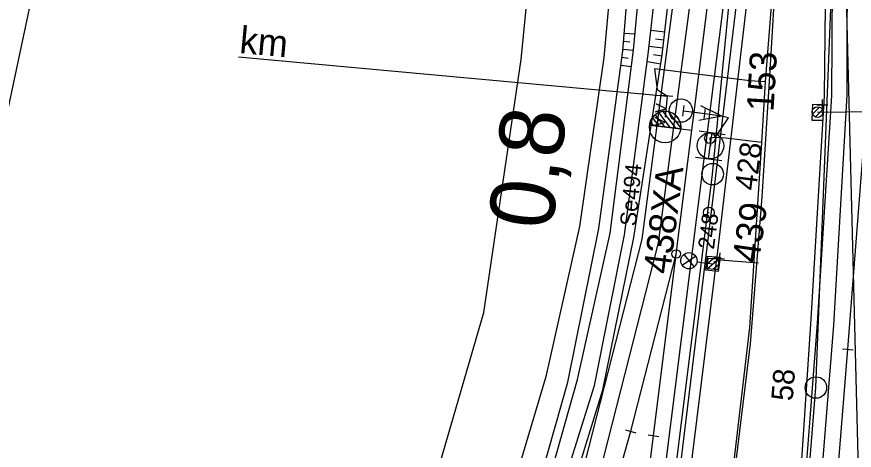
# Model space of a CAD drawing. Extents: x -598638 to -597933, y -1164002 to -1161904.
# Drawn here: x -598323.8 to -598246.1, y -1163278.4 to -1163238.1 of the extents above; entities that cross this region are included whole.
import ezdxf

# ---------------------------------------------------------------- set-up
doc = ezdxf.new("R2010")
doc.units = 0
for name, color, linetype in [('Vrstva 1', 7, 'Continuous'), ('Vrstva 11', 7, 'Continuous'), ('Vrstva 12', 7, 'Continuous'), ('Vrstva 2', 7, 'Continuous'), ('Vrstva 25', 7, 'Continuous'), ('Vrstva 26', 7, 'Continuous'), ('Vrstva 28', 7, 'Continuous'), ('Vrstva 3', 7, 'Continuous'), ('Vrstva 35', 7, 'Continuous'), ('Vrstva 4', 7, 'Continuous'), ('Vrstva 43', 7, 'Continuous'), ('Vrstva 44', 7, 'Continuous'), ('Vrstva 48', 7, 'Continuous'), ('Vrstva 49', 7, 'Continuous'), ('Vrstva 51', 7, 'Continuous'), ('Vrstva 6', 7, 'Continuous'), ('Vrstva 63', 7, 'Continuous'), ('Vrstva 7', 7, 'Continuous')]:
    doc.layers.add(name, color=color, linetype=linetype)

msp = doc.modelspace()

# ---------------------------------------------------------------- linework, layer by layer
at = {"layer": 'Vrstva 1'}
msp.add_line((-598246.649, -1163269.02), (-598244.89, -1163246.328), dxfattribs=at)
for points in [[(-598261.135, -1163248.665), (-598260.926, -1163246.987), (-598257.805, -1163221.972)], [(-598264.695, -1163277.054), (-598262.58, -1163260.169), (-598261.135, -1163248.665)], [(-598266.808, -1163276.648), (-598262.58, -1163260.169)], [(-598250.9, -1163321.936), (-598249.53, -1163304.978), (-598248.914, -1163297.297), (-598247.877, -1163284.361), (-598246.649, -1163269.02)], [(-598290.948, -1163362.176), (-598285.982, -1163344.65), (-598282.717, -1163333.052), (-598281.168, -1163327.552), (-598279.885, -1163323.01), (-598271.302, -1163292.589), (-598266.808, -1163276.648)], [(-598265.253, -1163281.456), (-598264.695, -1163277.054)]]:
    msp.add_lwpolyline(points, dxfattribs=at)
at = {"layer": 'Vrstva 11'}
for p, q in [((-598249.921, -1163247.154), (-598249.275, -1163246.508)), ((-598249.661, -1163247.424), (-598249.006, -1163246.769)), ((-598259.712, -1163261.53), (-598258.63, -1163260.626)), ((-598259.665, -1163261.003), (-598259.158, -1163260.579)), ((-598259.188, -1163261.58), (-598258.674, -1163261.151))]:
    msp.add_line(p, q, dxfattribs=at)
for points in [[(-598249.46, -1163246.97), (-598236.36, -1163246.81)], [(-598259.623, -1163260.537), (-598258.627, -1163260.627), (-598258.717, -1163261.623), (-598259.713, -1163261.533), (-598259.623, -1163260.537)]]:
    msp.add_lwpolyline(points, dxfattribs=at)
msp.add_lwpolyline([(-598259.623, -1163260.537), (-598258.627, -1163260.627), (-598258.717, -1163261.623), (-598259.713, -1163261.533)], close=True, dxfattribs=at)
msp.add_circle((-598249.46, -1163246.97), 0.5, dxfattribs=at)
at = {"layer": 'Vrstva 12'}
for points in [[(-598248.96, -1163246.25), (-598248.98, -1163247.75), (-598249.95, -1163247.76), (-598249.91, -1163246.24), (-598248.96, -1163246.25)], [(-598259.83, -1163261.68), (-598259.67, -1163260.38), (-598258.51, -1163260.47), (-598258.68, -1163261.8), (-598259.83, -1163261.68)]]:
    msp.add_lwpolyline(points, dxfattribs=at)
at = {"layer": 'Vrstva 2'}
for p, q in [((-598263.631, -1163248.354), (-598264.516, -1163247.213)), ((-598263.104, -1163248.421), (-598264.194, -1163247.018)), ((-598262.578, -1163248.487), (-598263.804, -1163246.909)), ((-598262.15, -1163248.427), (-598263.314, -1163246.927)), ((-598264.683, -1163248.221), (-598264.976, -1163247.845)), ((-598264.157, -1163248.287), (-598264.779, -1163247.486)), ((-598262.156, -1163248.54), (-598265.06, -1163248.174)), ((-598265.06, -1163248.174), (-598262.156, -1163248.539)), ((-598262.156, -1163248.539), (-598262.156, -1163248.54)), ((-598262.155, -1163248.54), (-598261.135, -1163248.665)), ((-598247.147, -1163268.98), (-598246.151, -1163269.06)), ((-598267.289, -1163276.512), (-598266.327, -1163276.784)), ((-598265.191, -1163276.991), (-598264.199, -1163277.117))]:
    msp.add_line(p, q, dxfattribs=at)
for points in [[(-598246.649, -1163269.02), (-598244.89, -1163246.328)], [(-598264.695, -1163277.054), (-598262.58, -1163260.169), (-598261.135, -1163248.665)], [(-598266.808, -1163276.648), (-598262.58, -1163260.169)]]:
    msp.add_lwpolyline(points, dxfattribs=at)
for centre, radius in [((-598263.616, -1163248.354), 1.462), ((-598262.585, -1163260.163), 0.4)]:
    msp.add_circle(centre, radius, dxfattribs=at)
msp.add_arc((-598263.608, -1163248.357), 1.464, 352.86023, 172.82108, dxfattribs=at)
at = {"layer": 'Vrstva 25'}
for p, q in [((-598259.5, -1163249.4), (-598259.4, -1163249.4)), ((-598262.029, -1163261.215), (-598260.785, -1163260.363)), ((-598261.885, -1163260.21), (-598260.915, -1163261.365)), ((-598260.658, -1163260.89), (-598259.17, -1163261.08))]:
    msp.add_line(p, q, dxfattribs=at)
for centre, radius in [((-598259.449, -1163249.397), 0.5), ((-598261.405, -1163260.792), 0.754)]:
    msp.add_circle(centre, radius, dxfattribs=at)
at = {"layer": 'Vrstva 26'}
for points in [[(-598273.816, -1163355.578), (-598271.677, -1163346.374), (-598270.289, -1163341.485), (-598268.518, -1163336.06), (-598265.457, -1163325.157), (-598262.629, -1163312.811), (-598258.667, -1163293.697), (-598257.35, -1163282.225), (-598255.678, -1163268.505), (-598254.603, -1163254.848), (-598253.891, -1163243.597), (-598253.428, -1163235.813)], [(-598254.944, -1163261.011), (-598258.507, -1163260.742), (-598259.131, -1163260.92)]]:
    msp.add_lwpolyline(points, dxfattribs=at)
at = {"layer": 'Vrstva 28'}
for points in [[(-598253.43, -1163232.8), (-598254.31, -1163244.16), (-598254.67, -1163249.79), (-598255.78, -1163266.99), (-598257.63, -1163282.82), (-598258.86, -1163294.68), (-598252.64, -1163294.8), (-598246.37, -1163296.02), (-598247.03, -1163297.8)], [(-598254.31, -1163244.16), (-598255.75, -1163244.05), (-598264.61, -1163242.96), (-598264.36, -1163244.88), (-598263.41, -1163245.48)], [(-598258.98, -1163249.34), (-598257.74, -1163247.49), (-598258.34, -1163247.34)], [(-598254.67, -1163249.79), (-598257.98, -1163249.4), (-598258.98, -1163249.34), (-598259.45, -1163249.4), (-598259.41, -1163250.1)]]:
    msp.add_lwpolyline(points, dxfattribs=at)
at = {"layer": 'Vrstva 3'}
for p, q in [((-598261.983, -1163247.353), (-598261.852, -1163246.361)), ((-598258.34, -1163247.34), (-598260.301, -1163246.383)), ((-598261.917, -1163246.857), (-598259.935, -1163247.117)), ((-598258.34, -1163247.34), (-598261.076, -1163246.976)), ((-598260, -1163247.613), (-598259.869, -1163246.621)), ((-598258.34, -1163247.34), (-598260.483, -1163247.751)), ((-598260.467, -1163248.715), (-598258.025, -1163249.043)), ((-598259.574, -1163251.321), (-598259.246, -1163248.879)), ((-598260.795, -1163251.157), (-598258.353, -1163251.485))]:
    msp.add_line(p, q, dxfattribs=at)
for centre, radius in [((-598262.154, -1163246.832), 1.084), ((-598259.409, -1163250.099), 1.232)]:
    msp.add_circle(centre, radius, dxfattribs=at)
at = {"layer": 'Vrstva 35'}
msp.add_lwpolyline([(-598255.75, -1163244.05), (-598264.61, -1163242.96)], dxfattribs=at)
at = {"layer": 'Vrstva 4'}
for points in [[(-598398.167, -1163553.239), (-598376.487, -1163515.918), (-598348.795, -1163467.979), (-598339.716, -1163452.202), (-598323.266, -1163423.236), (-598308.372, -1163396.471), (-598302.715, -1163384.123), (-598298.324, -1163372.137), (-598289.593, -1163344.221), (-598282.967, -1163321.229), (-598274.797, -1163290.285), (-598269.404, -1163272.781), (-598266.519, -1163258.633), (-598263.896, -1163241.651), (-598261.185, -1163218.05), (-598260.503, -1163217.001), (-598259.092, -1163201.513), (-598258.163, -1163186.176), (-598256.557, -1163141.317), (-598256.485, -1163129.008), (-598255.651, -1163108.451), (-598254.34, -1163087.718), (-598253.319, -1163075.132)], [(-598307.376, -1163503.64), (-598306.256, -1163500.72), (-598304.527, -1163496.743), (-598299.478, -1163486.144), (-598290.117, -1163465.204), (-598280.795, -1163442.724), (-598274.814, -1163425.66), (-598269.09, -1163405.616), (-598262.907, -1163380.487), (-598260.225, -1163366.071), (-598256.638, -1163342.661), (-598254.612, -1163322.432), (-598252.977, -1163304.928), (-598251.437, -1163287.268), (-598250.068, -1163266.224), (-598248.818, -1163245.446), (-598248.467, -1163214.545), (-598248.623, -1163173.63), (-598248.072, -1163131.254), (-598247.596, -1163128.349)], [(-598388.69, -1163572.819), (-598382.701, -1163561.089), (-598361.383, -1163524.292), (-598334.6, -1163477.579), (-598308.353, -1163432.12), (-598292.471, -1163404.257), (-598285.937, -1163390.16), (-598281.631, -1163378.652), (-598277.216, -1163365.008), (-598272.579, -1163348.284), (-598269.387, -1163336.75), (-598267.113, -1163324.869), (-598262.674, -1163291.919), (-598258.642, -1163259.137), (-598254.182, -1163220.99), (-598251.647, -1163201.068), (-598250.766, -1163187.503), (-598249.671, -1163144.519), (-598248.922, -1163130.776), (-598248.69, -1163130.313)]]:
    msp.add_lwpolyline(points, dxfattribs=at)
at = {"layer": 'Vrstva 43'}
for centre in [(-598259.208, -1163252.741), (-598249.615, -1163272.581)]:
    msp.add_circle(centre, 1, dxfattribs=at)
at = {"layer": 'Vrstva 44'}
for points in [[(-598295.758, -1163493.483), (-598278.118, -1163452.874), (-598264.209, -1163410.565), (-598254.468, -1163367.19), (-598248.62, -1163321.577), (-598253.497, -1163320.887), (-598249.615, -1163272.581), (-598247.635, -1163222.481), (-598247.486, -1163176.779), (-598247.442, -1163130.148), (-598244.014, -1163084.171), (-598235.33, -1163037.762), (-598224.817, -1163002.559), (-598219.379, -1163002.169), (-598206.652, -1162968.487), (-598191.401, -1162936.053), (-598173.754, -1162904.506), (-598155.689, -1162873.083), (-598136.14, -1162838.446), (-598116.776, -1162804.197)], [(-598280.199, -1163332.648), (-598271.397, -1163301.809), (-598265.446, -1163302.712), (-598259.208, -1163252.741), (-598251.788, -1163176.385), (-598250.383, -1163130.296), (-598247.948, -1163083.491), (-598241.007, -1163044.927)]]:
    msp.add_lwpolyline(points, dxfattribs=at)
at = {"layer": 'Vrstva 48'}
for p, q in [((-598264.949, -1163239.347), (-598263.648, -1163239.496)), ((-598266.416, -1163239.741), (-598267.414, -1163239.661)), ((-598264.513, -1163240.151), (-598263.734, -1163240.241)), ((-598266.881, -1163240.456), (-598267.474, -1163240.409)), ((-598265.116, -1163240.837), (-598263.82, -1163240.986)), ((-598266.555, -1163241.235), (-598267.534, -1163241.156)), ((-598264.681, -1163241.611), (-598263.908, -1163241.731)), ((-598267.045, -1163241.979), (-598267.627, -1163241.9)), ((-598265.294, -1163242.275), (-598264.023, -1163242.472)), ((-598266.752, -1163242.775), (-598267.727, -1163242.644))]:
    msp.add_line(p, q, dxfattribs=at)
at = {"layer": 'Vrstva 49'}
for points in [[(-598299.445, -1163361.058), (-598297.068, -1163359.059), (-598293.068, -1163343.621), (-598287.79, -1163320.649), (-598279.637, -1163288.312), (-598274.636, -1163271.434), (-598271.523, -1163257.595), (-598269.283, -1163241.904), (-598267.104, -1163218.072), (-598264.127, -1163206.783), (-598263.144, -1163204.971), (-598260.62, -1163202.843), (-598259.578, -1163186.018), (-598258.253, -1163141.176), (-598259.192, -1163127.718), (-598260.075, -1163119.279), (-598261.182, -1163115.692), (-598261.349, -1163113.122), (-598258.894, -1163101.538), (-598255.65, -1163087.809), (-598254.518, -1163075.132), (-598252.098, -1163061.479), (-598247.841, -1163044.835)], [(-598309.446, -1163203.262), (-598316.229, -1163215.539), (-598313.873, -1163217.741), (-598321.933, -1163233.799), (-598326.308, -1163254.29), (-598324.871, -1163281.374), (-598324.668, -1163290.005), (-598320.258, -1163307.426), (-598325.507, -1163312.636), (-598323.584, -1163327.934), (-598325.353, -1163339.082), (-598298.967, -1163343.623), (-598293.544, -1163316.86), (-598287.625, -1163290.34), (-598280.443, -1163265.616), (-598276.989, -1163242.095), (-598274.987, -1163221.639), (-598274.592, -1163211.298), (-598290.163, -1163206.434), (-598302.523, -1163205.338), (-598306.323, -1163207.572)], [(-598350.075, -1163469.161), (-598350.962, -1163468.642), (-598341.128, -1163451.449), (-598324.91, -1163422.41), (-598309.936, -1163395.461), (-598304.358, -1163383.215), (-598300.139, -1163371.399), (-598292.224, -1163343.911), (-598285.916, -1163320.98), (-598277.492, -1163289.124), (-598272.642, -1163272.084), (-598269.771, -1163257.778), (-598267.544, -1163241.285), (-598265.728, -1163218.657), (-598264.511, -1163217.412), (-598261.185, -1163218.05)], [(-598350.962, -1163468.642), (-598340.803, -1163451.583), (-598324.406, -1163422.648), (-598309.58, -1163395.796), (-598303.887, -1163383.446), (-598299.666, -1163371.582), (-598291.401, -1163343.859), (-598285.02, -1163321.209), (-598276.751, -1163289.495), (-598271.739, -1163271.843), (-598268.729, -1163258.218), (-598266.553, -1163241.22), (-598264.463, -1163218.64)], [(-598350.075, -1163469.161), (-598340.252, -1163451.87), (-598323.84, -1163422.849), (-598308.915, -1163396.15), (-598303.181, -1163383.749), (-598299.003, -1163371.924), (-598290.374, -1163343.997), (-598283.872, -1163321.586), (-598275.648, -1163289.867), (-598270.185, -1163272.379), (-598267.391, -1163258.396), (-598265.172, -1163241.341), (-598262.635, -1163218.663), (-598264.463, -1163218.64)]]:
    msp.add_lwpolyline(points, dxfattribs=at)
at = {"layer": 'Vrstva 51'}
for points in [[(-598397.431, -1163553.318), (-598375.745, -1163515.943), (-598348.098, -1163468.333), (-598322.38, -1163423.533), (-598307.542, -1163396.818), (-598301.86, -1163384.541), (-598297.285, -1163372.341), (-598293.283, -1163359.379), (-598288.845, -1163344.448), (-598282.25, -1163321.235), (-598273.825, -1163290.423), (-598265.756, -1163258.778), (-598260.545, -1163219.203), (-598259.744, -1163217.171), (-598258.57, -1163201.891), (-598257.659, -1163186.255), (-598256.038, -1163142.193), (-598255.793, -1163128.623), (-598255.065, -1163108.27), (-598253.781, -1163088.998), (-598252.62, -1163075.466)], [(-598396.078, -1163554.151), (-598374.443, -1163516.599), (-598347.031, -1163469.014), (-598321.218, -1163424.261), (-598306.253, -1163397.723), (-598300.608, -1163385.153), (-598295.814, -1163372.93), (-598291.849, -1163359.988), (-598287.46, -1163344.41), (-598281.154, -1163322.32), (-598272.412, -1163291.197), (-598264.229, -1163259.135), (-598258.972, -1163219.27), (-598257.327, -1163201.644), (-598256.369, -1163186.491), (-598254.79, -1163142.649), (-598254.397, -1163128.629), (-598253.571, -1163108.317), (-598252.585, -1163090.153), (-598250.983, -1163076.012)], [(-598384.985, -1163560.822), (-598363.176, -1163523.063), (-598335.955, -1163475.581), (-598310.179, -1163431.066), (-598295.149, -1163404.135), (-598288.465, -1163389.583), (-598283.96, -1163377.815), (-598279.772, -1163364.473), (-598275.196, -1163348.33), (-598271.933, -1163336.198), (-598269.31, -1163324.265), (-598265.084, -1163292.029), (-598261.053, -1163259.678), (-598256.104, -1163220.296), (-598254.426, -1163201.671), (-598253.667, -1163187.936), (-598252.018, -1163143.494), (-598251.534, -1163128.863), (-598250.791, -1163108.998), (-598250.069, -1163094.383), (-598248.218, -1163076.729)], [(-598305.922, -1163504.285), (-598297.335, -1163487.137), (-598287.92, -1163465.981), (-598279.035, -1163443.103), (-598273.208, -1163425.978), (-598267.2, -1163406.108), (-598261.011, -1163380.887), (-598258.166, -1163366.304), (-598254.569, -1163343.143), (-598252.435, -1163322.084), (-598250.965, -1163305.051), (-598249.488, -1163286.133), (-598247.962, -1163266.793), (-598246.718, -1163245.404), (-598246.637, -1163214.417), (-598246.633, -1163173.748), (-598246.347, -1163129.422), (-598245.484, -1163112.939), (-598244.076, -1163096.672), (-598241.475, -1163076.865)], [(-598298.888, -1163486.593), (-598289.113, -1163465.583), (-598279.905, -1163442.964), (-598274.107, -1163425.699), (-598268.268, -1163405.757), (-598262.238, -1163380.596), (-598259.701, -1163366.461), (-598255.999, -1163342.847), (-598253.859, -1163322.319), (-598252.407, -1163304.609), (-598250.982, -1163286.31), (-598249.458, -1163266.6), (-598248.128, -1163245.447), (-598247.963, -1163214.31), (-598248.01, -1163173.778), (-598247.475, -1163130.652), (-598247.596, -1163128.349), (-598246.685, -1163112.866), (-598245.177, -1163096.514), (-598242.921, -1163076.624)], [(-598389.422, -1163572.47), (-598383.242, -1163561.018), (-598361.933, -1163523.985), (-598335.337, -1163477.363), (-598309.065, -1163431.797), (-598293.626, -1163404.644), (-598286.924, -1163390.082), (-598282.523, -1163378.361), (-598278.252, -1163364.663), (-598273.758, -1163348.557), (-598270.372, -1163336.656), (-598267.892, -1163324.623), (-598263.657, -1163291.858), (-598259.724, -1163259.57), (-598255.007, -1163220.516), (-598252.865, -1163201.196), (-598252.034, -1163187.935), (-598250.643, -1163143.798), (-598250.023, -1163129.244), (-598249.184, -1163109.078), (-598248.423, -1163094.475), (-598246.693, -1163077.089)]]:
    msp.add_lwpolyline(points, dxfattribs=at)
at = {"layer": 'Vrstva 6'}
for p, q in [((-598303.243, -1163241.819), (-598263.41, -1163245.48)), ((-598262.913, -1163245.526), (-598263.908, -1163245.435)), ((-598263.591, -1163247.452), (-598263.41, -1163245.48))]:
    msp.add_line(p, q, dxfattribs=at)
at = {"layer": 'Vrstva 63'}
msp.add_line((-598243.435, -1163367.735), (-598248.331, -1163175.227), dxfattribs=at)
at = {"layer": 'Vrstva 7'}
for p, q in [((-598249.519, -1163246.287), (-598248.519, -1163246.287)), ((-598249.019, -1163245.787), (-598249.019, -1163246.787)), ((-598259.612, -1163256.317), (-598259.512, -1163256.317)), ((-598258.534, -1163260.053), (-598258.642, -1163261.047)), ((-598259.085, -1163260.496), (-598258.091, -1163260.604))]:
    msp.add_line(p, q, dxfattribs=at)
msp.add_circle((-598259.562, -1163256.317), 0.5, dxfattribs=at)

# ---------------------------------------------------------------- texts
at = {"layer": 'Vrstva 11'}
for s, rotation, p in [('153', 86.53177, (-598253.558, -1163246.97)), ('439', 81.83655, (-598254.912, -1163261.08))]:
    msp.add_text(s, height=2.5, rotation=rotation, dxfattribs=at).set_placement(p)
at = {"layer": 'Vrstva 2'}
msp.add_text('438XA', height=2.5, rotation=82.84063, dxfattribs=at).set_placement((-598263.166, -1163262.101))
at = {"layer": 'Vrstva 25'}
msp.add_text('248', height=1.5, rotation=82.7161, dxfattribs=at).set_placement((-598259.084, -1163259.785))
at = {"layer": 'Vrstva 43'}
for s, rotation, p in [('428', 82.84066, (-598255.174, -1163254.327)), ('58', 85.42341, (-598251.776, -1163273.878))]:
    msp.add_text(s, height=2, rotation=rotation, dxfattribs=at).set_placement(p)
at = {"layer": 'Vrstva 6'}
for s, height, rotation, p in [('km ', 2.5, 354.74862, (-598303.206, -1163241.478)), ('  A A', 1, 264.74862, (-598264.406, -1163245.388)), ('Se494', 1.5, 84.74862, (-598266.321, -1163257.622))]:
    msp.add_text(s, height=height, rotation=rotation, dxfattribs=at).set_placement(p)
at = {"layer": 'Vrstva 7'}
msp.add_text('0,8', height=6, rotation=82.84066, dxfattribs=at).set_placement((-598274.124, -1163258.046))

doc.saveas('drawing.dxf')
